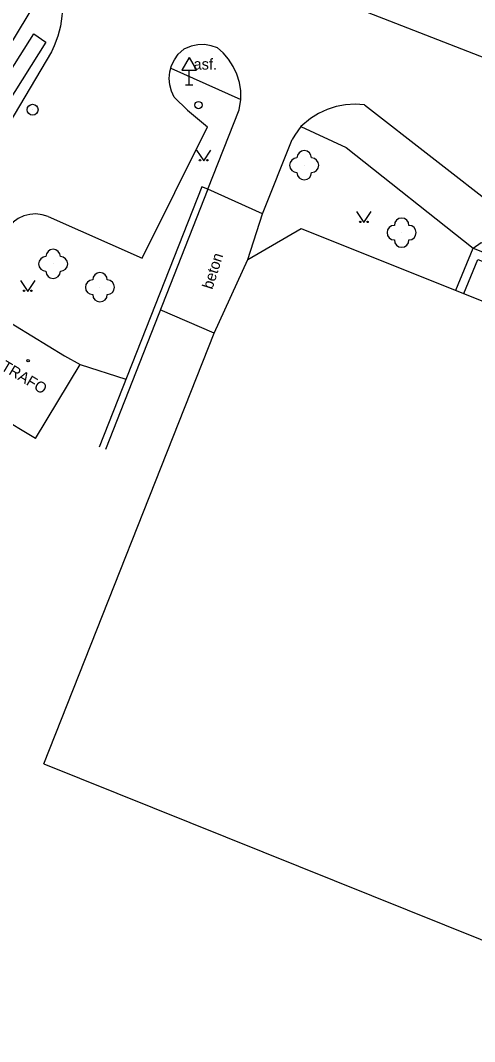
# Model space of a CAD drawing. Extents: x -584400 to -581602, y -1210894 to -1208793.
# Drawn here: x -583374.3 to -583343.1, y -1210558 to -1210488 of the extents above; entities that cross this region are included whole.
import ezdxf

# ---------------------------------------------------------------- set-up
doc = ezdxf.new("R2010")
doc.units = 0
for name, color, linetype in [('BUDOVY_MĚŘ', 7, 'Continuous'), ('MAP_ZN_BP', 7, 'Continuous'), ('POMOC_POPIS', 7, 'Continuous'), ('ROZHRANÍ_PLOCH', 7, 'Continuous'), ('ZELEŇ', 7, 'Continuous'), ('ZN_BUDOV', 7, 'Continuous'), ('ZN_DOPLŇKOVÉ', 7, 'Continuous'), ('ZN_KULTUR', 7, 'Continuous')]:
    doc.layers.add(name, color=color, linetype=linetype)

msp = doc.modelspace()

# ---------------------------------------------------------------- linework, layer by layer
at = {"layer": 'BUDOVY_MĚŘ'}
for points in [[(-583358.67, -1210504.38), (-583355.01, -1210502.25), (-583339.78, -1210508.36)], [(-583360.99, -1210509.42), (-583358.67, -1210504.38)], [(-583379.04, -1210508.79), (-583377.98, -1210506.87), (-583371.24, -1210510.97), (-583370.18, -1210511.58)], [(-583372.65, -1210538.93), (-583360.99, -1210509.42)], [(-583373.23, -1210516.64), (-583381.01, -1210511.99), (-583380.07, -1210510.52), (-583379.77, -1210510.01)], [(-583373.23, -1210516.64), (-583370.18, -1210511.58)], [(-583372.65, -1210538.93), (-583325.3, -1210557.96)]]:
    msp.add_lwpolyline(points, dxfattribs=at)
at = {"layer": 'MAP_ZN_BP'}
for radius in [0.375, 0.0005]:
    msp.add_circle((-583373.43, -1210494.121), radius, dxfattribs=at)
at = {"layer": 'ROZHRANÍ_PLOCH'}
for points in [[(-583348.95, -1210488.05), (-583367.37, -1210480.88), (-583368.02, -1210480.61), (-583368.64, -1210480.27), (-583369.21, -1210479.87), (-583369.73, -1210479.4), (-583370.2, -1210478.87), (-583370.6, -1210478.3), (-583370.93, -1210477.68), (-583371.2, -1210477.03), (-583371.38, -1210476.36), (-583371.49, -1210475.67), (-583371.52, -1210474.97), (-583371.47, -1210474.27), (-583371.35, -1210473.63), (-583354.33, -1210426.52), (-583320.25, -1210332.6)], [(-583373.22, -1210486.77), (-583383.1, -1210503.05), (-583383.8, -1210504.18), (-583384.56, -1210505.27), (-583385.39, -1210506.31), (-583386.28, -1210507.29), (-583387.23, -1210508.22), (-583388.23, -1210509.1), (-583389.28, -1210509.91), (-583390.38, -1210510.65), (-583391.61, -1210511.38)], [(-583371.4, -1210487.48), (-583371.42, -1210487.7), (-583371.52, -1210488.4), (-583371.69, -1210489.09), (-583371.94, -1210489.75), (-583372.14, -1210490.15), (-583375.06, -1210495.09)], [(-583324.28, -1210494.67), (-583324.32, -1210494.7), (-583324.91, -1210495.07), (-583325.53, -1210495.37), (-583326.18, -1210495.6), (-583326.86, -1210495.75), (-583327.55, -1210495.82), (-583328.24, -1210495.82), (-583328.93, -1210495.73), (-583329.9, -1210495.46), (-583348.95, -1210488.05)], [(-583359.15, -1210493.41), (-583359.16, -1210492.82), (-583359.25, -1210492.25), (-583359.42, -1210491.69), (-583359.67, -1210491.16), (-583359.99, -1210490.66), (-583360.37, -1210490.22), (-583360.75, -1210489.88), (-583361.18, -1210489.73), (-583361.64, -1210489.66), (-583362.1, -1210489.67), (-583362.55, -1210489.76), (-583363.06, -1210489.97)], [(-583363.72, -1210493.26), (-583363.91, -1210492.85), (-583364.02, -1210492.42), (-583364.06, -1210491.97), (-583364.02, -1210491.52), (-583363.9, -1210491.09), (-583363.7, -1210490.69), (-583363.44, -1210490.32), (-583363.06, -1210489.97)], [(-583363.96, -1210491.28), (-583359.15, -1210493.41)], [(-583363.72, -1210493.26), (-583362.8, -1210494.14), (-583361.43, -1210495.28)], [(-583361.41, -1210499.55), (-583359.26, -1210494.13), (-583359.15, -1210493.41)], [(-583350.67, -1210493.78), (-583351.32, -1210493.74), (-583351.97, -1210493.78), (-583352.61, -1210493.9), (-583353.23, -1210494.1), (-583353.82, -1210494.37), (-583354.37, -1210494.71), (-583355.04, -1210495.27)], [(-583350.67, -1210493.78), (-583341.4, -1210500.99), (-583306.67, -1210514.38), (-583306.29, -1210514.61), (-583305.95, -1210514.9), (-583305.67, -1210515.24), (-583305.46, -1210515.64), (-583305.31, -1210516.06), (-583305.25, -1210516.5), (-583305.3, -1210517.12), (-583306.75, -1210520.95)], [(-583365.92, -1210504.28), (-583361.43, -1210495.28)], [(-583355.04, -1210495.27), (-583355.45, -1210495.85), (-583355.63, -1210496.16)], [(-583355.04, -1210495.27), (-583351.94, -1210496.7), (-583343.23, -1210503.61)], [(-583357.68, -1210501.25), (-583355.63, -1210496.16)], [(-583357.68, -1210501.25), (-583361.41, -1210499.55)], [(-583372.37, -1210501.43), (-583372.78, -1210501.31), (-583373.2, -1210501.26), (-583373.63, -1210501.29), (-583374.04, -1210501.39), (-583374.43, -1210501.58), (-583374.77, -1210501.83), (-583375.18, -1210502.31), (-583377.98, -1210506.87)], [(-583372.37, -1210501.43), (-583365.92, -1210504.28)], [(-583358.67, -1210504.38), (-583357.68, -1210501.25)], [(-583344.42, -1210506.49), (-583343.23, -1210503.61)], [(-583343.23, -1210503.61), (-583342.67, -1210503.22), (-583330.38, -1210508.06)], [(-583343.23, -1210503.61), (-583330.05, -1210508.83)], [(-583343.87, -1210506.72), (-583342.9, -1210504.38), (-583314.65, -1210515.58)]]:
    msp.add_lwpolyline(points, dxfattribs=at)
at = {"layer": 'ZELEŇ'}
for centre in [(-583354.81, -1210497.92), (-583348.13, -1210502.54), (-583372.02, -1210504.68), (-583368.81, -1210506.28)]:
    msp.add_circle(centre, 0.0005, dxfattribs=at)
for centre, start, end in [((-583355.31, -1210497.92), 89.99999, 269.99999), ((-583354.81, -1210497.42), 0, 179.99999), ((-583354.31, -1210497.92), 270, 89.99999), ((-583354.81, -1210498.42), 179.99999, 359.99999), ((-583348.13, -1210502.04), 0, 179.99999), ((-583348.63, -1210502.54), 89.99999, 269.99999), ((-583347.63, -1210502.54), 270, 89.99999), ((-583348.13, -1210503.04), 179.99999, 359.99999), ((-583372.02, -1210504.18), 0, 179.99999), ((-583372.52, -1210504.68), 89.99999, 269.99999), ((-583371.52, -1210504.68), 270, 89.99999), ((-583372.02, -1210505.18), 179.99999, 359.99999), ((-583368.81, -1210505.78), 0, 179.99999), ((-583369.31, -1210506.28), 89.99999, 269.99999), ((-583368.31, -1210506.28), 270, 89.99999), ((-583368.81, -1210506.78), 179.99999, 359.99999)]:
    msp.add_arc(centre, 0.5, start, end, dxfattribs=at)
at = {"layer": 'ZN_BUDOV'}
msp.add_circle((-583373.74, -1210511.31), 0.0875, dxfattribs=at)
at = {"layer": 'ZN_DOPLŇKOVÉ'}
for p, q in [((-583362.7, -1210490.544), (-583363.2, -1210491.41)), ((-583362.7, -1210490.544), (-583362.2, -1210491.41)), ((-583363.2, -1210491.41), (-583362.2, -1210491.41)), ((-583362.7, -1210492.41), (-583362.7, -1210491.41)), ((-583362.95, -1210492.41), (-583362.45, -1210492.41))]:
    msp.add_line(p, q, dxfattribs=at)
for points in [[(-583389.83, -1210515), (-583373.35, -1210488.93), (-583372.52, -1210489.49), (-583375.15, -1210493.66), (-583378.75, -1210499.62), (-583386.29, -1210511.43), (-583389.38, -1210515.92)], [(-583361.41, -1210499.55), (-583361.83, -1210499.39), (-583368.86, -1210517.23)], [(-583361.41, -1210499.55), (-583368.44, -1210517.4)], [(-583360.99, -1210509.42), (-583364.68, -1210507.83)], [(-583370.18, -1210511.58), (-583367.03, -1210512.57)]]:
    msp.add_lwpolyline(points, dxfattribs=at)
for radius in [0.25, 0.0005]:
    msp.add_circle((-583362.06, -1210493.8), radius, dxfattribs=at)
at = {"layer": 'ZN_KULTUR'}
for points in [[(-583362.2, -1210496.88), (-583361.7, -1210497.63), (-583361.2, -1210496.88)], [(-583351.22, -1210501.1), (-583350.72, -1210501.85), (-583350.22, -1210501.1)], [(-583374.26, -1210505.82), (-583373.76, -1210506.57), (-583373.26, -1210505.82)]]:
    msp.add_lwpolyline(points, dxfattribs=at)
for centre in [(-583361.95, -1210497.58), (-583361.45, -1210497.58), (-583350.97, -1210501.8), (-583350.47, -1210501.8), (-583374.01, -1210506.52), (-583373.51, -1210506.52)]:
    msp.add_circle(centre, 0.05, dxfattribs=at)

# ---------------------------------------------------------------- texts
at = {"layer": 'POMOC_POPIS'}
msp.add_text('asf.', height=0.75, dxfattribs=at).set_placement((-583362.4, -1210491.37))
for s, rotation, p in [('beton', 72.44816, (-583361.11, -1210506.47)), ('TRAFO', 329.18333, (-583375.65, -1210511.9))]:
    msp.add_text(s, height=0.75, rotation=rotation, dxfattribs=at).set_placement(p)

doc.saveas('drawing.dxf')
